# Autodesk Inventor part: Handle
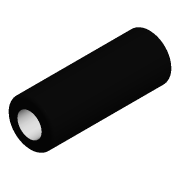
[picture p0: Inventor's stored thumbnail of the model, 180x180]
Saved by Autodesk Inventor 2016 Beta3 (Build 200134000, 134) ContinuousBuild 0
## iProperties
Created: 2016-02
Part Number: Handle
Material: ABS Plastic
Document SubType Name: Modeling
Designer: Vertex
Density: 1.06 g/cm^3
Appearance: Smooth - White
Mass: 42.7251 g
Surface Area: 124.073 cm^2
Volume: 40.3067 cm^3
Author: Vertex
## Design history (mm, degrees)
sketch "Sketch1"
  geometry: C1 r 8 at (0, 0); C2 r 15 at (0, 0); 1 further point
  constraints: 2 centre point, 2 coincident
  dimensions: "d0" = 16 diameter of C1; "d1" = 30 diameter of C2
extrude "Extrusion1" new body sketch "Sketch1" distance "d2" = 80; taper "d3" = 0 deg
fillet "Fillet1" dims "d4" = 2
body "Solid1"
